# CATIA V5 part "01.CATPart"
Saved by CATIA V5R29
Part number: 01
Bounding box of the stored display mesh (mm): x -24 to 24, y -32.5 to 32.5, z 0 to 8
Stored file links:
  C:\Users\FERIDUN\Desktop\montaj2\01.CATPart
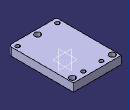
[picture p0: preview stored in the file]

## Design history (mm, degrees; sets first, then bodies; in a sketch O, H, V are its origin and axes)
Body1 (main body)
  Sketch1 on xy-plane, origin (0, 0, 0), H (1, 0, 0), V (0, 1, 0)
    line L1 (24, 32.5) -> (24, -32.5)
    line L2 (24, -32.5) -> (-24, -32.5)
    line L3 (-24, -32.5) -> (-24, 32.5)
    line L4 (-24, 32.5) -> (24, 32.5)
    circle A1 centre (-20, 27.5) radius 3
    point P5 (-20, 27.5)
    circle A2 centre (-20, -27.5) radius 2
    point P6 (-20, -27.5)
    point P7 (20, 27.5)
    point P8 (20, -27.5)
    circle A3 centre (20, 27.5) radius 3
    circle A4 centre (20, -27.5) radius 2
    circle A5 centre (-9, 27.5) radius 2
    point P9 (-9, 27.5)
    point P10 (9, 27.5)
    circle A6 centre (9, 27.5) radius 2
    circle A7 centre (0, -27.5) radius 3
    point P11 (0, -27.5)
    distance L1 L3 = 48
    distance L2 L4 = 65
    radius A1 = 3
    radius A2 = 2
    distance P5 L4 = 5
    distance P5 P7 = 40
    distance P6 P8 = 40
    distance P5 P6 = 55
    radius A5 = 2
    distance P9 P10 = 18
    distance P9 L4 = 5
    radius A7 = 3
    distance P11 L2 = 5
    vertical: L1 V, L3 V
    horizontal: L2 H, L4 H
    equidistance: L1 L3 O, L2 L4 O
    symmetry: A1 A3 V, A2 A4 V, A5 A6 V
    coincidence: P11 V
  Pad1: profile Sketch1, direction (0, 0, 1), length 8
  Fillet1: radius 2.5, on edge [face of Pad1 from Sketch1.L1 | face of Pad1 from Sketch1.L2]; edge [face of Pad1 from Sketch1.L2 | face of Pad1 from Sketch1.L3]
